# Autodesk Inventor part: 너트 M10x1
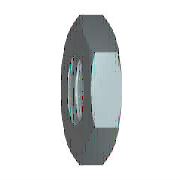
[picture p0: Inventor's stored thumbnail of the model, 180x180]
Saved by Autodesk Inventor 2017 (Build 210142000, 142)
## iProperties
Created: 2012-02
Part Number: 너트 M10x1
Material: 강철, 연강
Description: 6각 가는 너트 - 이중 모따기(부품 등급 A) - 정밀 나사산
Document SubType Name: Modeling
Standard: JIS B 1181
Designer: mduedu
Standards Organization: JIS
Language: ko-KR
Size Designation: M10x1
Categories: <MemberInstance><Categories><Category DisplayName="조임쇠" InternalName="e4da775c-781d-43d5-af7c-5136215cf5a6" Mnemonic="FSTN"><Category DisplayName="너트" InternalN
Density: 7.85 g/cm^3
Appearance: 강철
Mass: 6.12359 g
Surface Area: 6.99154 cm^2
Volume: 0.780075 cm^3
IsCustomPart: 1
Author: mduedu
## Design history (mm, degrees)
node "MSC_A1"
node "MSC_PT1"
node "MSC_PT2"
node "MSC_PF1"
body "Solid1"
sketch "스케치1"
  geometry: L1 (8, 4.619)-(8, -4.619); L2 (8, -4.619)-(0, -9.238); L3 (0, -9.238)-(-8, -4.619); L4 (-8, -4.619)-(-8, 4.619); L5 (-8, 4.619)-(0, 9.238); L6 (0, 9.238)-(8, 4.619); C1 r 8 at (0, 0); 2 further points
  constraints: 12 end point, 2 coincident, 1 centre point, 1 tangent, 1 vertical, 11 other
  dimensions: "d0" = 16 diameter of C1 (= ParS)
extrude "돌출1" new body sketch "스케치1" distance "d1" = 5 (= M); taper "d2" = 0 deg
sketch "스케치2"
  geometry: L1 (-8, 4.619)-(0, 9.238) reference; L2 (0, -9.238)-(-8, -4.619) reference; L3 (-8, 4.619)-(8, -4.619); L4 (-8, -4.619)-(8, 4.619); 1 further point
  constraints: 4 end point, 2 midpoint, 2 parallel
hole "구멍1" sketch "스케치2" diameter "d3" = 8.91747; stored, may be unused: countersink angle "d7" = 90 deg, drill point angle "d9" = 118 deg; dims "d4" = 6, "d5" = 4, "d6" = 2, "d8" = 8
chamfer "모따기1" distance "d10" = 0.5 (= 0.5 x PTC); stored, may be unused: second distance "d11" = 2, angle "d12" = 45 deg
revolve "회전1" stored, may be unused: angle "d15" = 90 deg
sketch "스케치3"
  geometry: L1 (-9.238, 5)-(-9.238, 4.285); L2 (-9.238, 4.285)-(-8, 5); L3 (-8, 5)-(-9.238, 5); L4 (-9.238, 0.715)-(-9.238, 0); L5 (-9.238, 0)-(-8, 0); L6 (-8, 0)-(-9.238, 0.715); L7 (0, 6)-(0, -1) reference; L8 (-4.619, 5)-(-9.238, 5) reference; L9 (-4.619, 0)-(-9.238, 0) reference; L10 (-9.238, 0)-(-9.238, 5) reference
  constraints: 12 end point, 4 collinear, 3 perpendicular, 2 equal length, 1 vertical
  dimensions: "d13" = 30 deg angle of L2 L3; "d14" = 8 distance from line of L2.end L7 (= 0.5 x ParS)
other parameters: "ParS" = 16 [user parameter; used in 2 equation terms], "M" = 5 [user parameter; used in 1 equation term], "PTC" = 1 [user parameter; used in 1 equation term], "d17" = 0, "d18" = 0, "d19" = 0, "d20" = 0, "d21" = 0, "d22" = 0, "d23" = 0
